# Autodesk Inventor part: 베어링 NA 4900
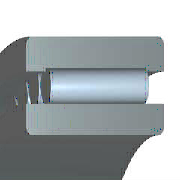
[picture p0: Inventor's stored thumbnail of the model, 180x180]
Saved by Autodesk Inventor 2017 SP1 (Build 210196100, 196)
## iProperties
Created: 2021-07
Part Number: 베어링 NA 4900
Material: 강철, 연강
Description: 니들 롤러 베어링 - 경계 치수 및 공차
Document SubType Name: Modeling
Standard: KS B 2029
Designer: mdu
Standards Organization: KS
Language: ko-KR
Size Designation: NA 4900 - 10 x 22 x 13
Categories: <MemberInstance><Categories><Category DisplayName="샤프트 부품" InternalName="7f7aeb1f-a693-4053-b835-cee3144e0d98" Mnemonic="SHFT"><Category DisplayName="베어링" Inter
Density: 7.86 g/cm^3
Mass: 23.8214 g
Surface Area: 38.613 cm^2
Volume: 3.03071 cm^3
Appearance: 베이지색
IsCustomPart: 0
Author: mdu
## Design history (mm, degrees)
sketch "스케치"
  geometry: L1 (1.857, 9)-(11.143, 9); L2 (11.143, 9)-(11.143, 7); L3 (13, 7)-(0, 7); L4 (1.857, 7)-(1.857, 9); L5 (1.857, 8)-(11.143, 8); L6 (6.5, 8)-(6.5, 7); L7 (0, 5)-(13, 5); L8 (0, 11)-(13, 11); L9 (13, 5)-(13, 7); L10 (13, 8.8)-(13, 11); L11 (1.857, 8.8)-(0, 8.8); L12 (11.143, 8.8)-(13, 8.8); L13 (-6, 0)-(36, 0) reference; L14 (0, -1.9)-(0, 14.9) reference
  constraints: 24 end point, 8 point on line, 3 midpoint, 3 parallel, 3 perpendicular, 2 symmetric about line, 1 horizontal, 1 other
  dimensions: "d6" = 10 diameter of L7 L13 (= WD); "d7" = 14 diameter of L3 L13 (= KID1); "d8" = 22 diameter of L8 L13 (= BD); "d9" = 16 diameter of L6.start L13 (= 0.5 x WD + 0.5 x BD); "d10" = 17.6 diameter of L12 L13 (= 0.9 x BD + 0.9 x WD - 0.8 x KID1); "d11" = 18 diameter of L1 L13 (= BD + WD - KID1); "d12" = 1.85714 distance between parallel lines of L14 L4 (= 0.142857 x KB); "d13" = 13 distance between parallel lines of L14 L9 (= KB); "d14" = 11.14286 distance between parallel lines of L14 L2 (= 0.857143 x KB)
revolve "본체" stored, may be unused: angle "d17" = 90 deg
revolve "롤러" stored, may be unused: angle "d18" = 90 deg
pattern_circular "IDS_ARRAYROLLER[SIMPL:T]" dims angle "d2" = 360 deg
body "Solid1"
fillet "모깎기1" dims "d0" = 0.3 (= KRS)
other parameters: "WD" = 10 [user parameter; used in 6 equation terms], "BD" = 22 [user parameter; used in 6 equation terms], "KB" = 13 [user parameter; used in 3 equation terms], "KID1" = 14 [user parameter; used in 4 equation terms], "KRS" = 0.3 [user parameter; used in 1 equation term], "d3" = 0, "d4" = 0, "d5" = 0, "d15" = 0, "d16" = 0, "BC0" = 9150000 [user parameter], "WR" = 5 (= 0.5 x WD) [user parameter], "BBA" = 0 [user parameter], "BC" = 8150000 [user parameter], "BR" = 11 (= 0.5 x BD) [user parameter]
